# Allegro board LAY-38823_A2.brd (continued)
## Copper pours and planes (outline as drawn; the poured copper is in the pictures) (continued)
VSYS_5V on TOP (solid shape): 23.42,5.23 23.42,3.94 23.57,3.79 23.93,3.79 23.94,3.78 23.94,1.51 22.94,1.51 22.05,1.52 22.05,5.18 22.05,5.18 22.05,5.23 22.1,5.28 23.37,5.28
VSYS_5V on BOTTOM (solid shape): 22.15,5.44 22.35,5.44 22.35,6.28 22.55,6.28 22.55,5.44 22.75,5.44 22.75,6.28 22.95,6.28 22.95,5.44 23.15,5.44 23.15,6.28 23.35,6.28 23.35,4.17 21.95,4.17 21.95,6.28 22.15,6.28
VSYS_5V on BOTTOM (solid shape): 22.89,13.18 22.89,11.01 22.89,11.01 22.89,10.86 23.35,10.4 23.35,8.65 23.15,8.65 23.15,9.49 22.95,9.49 22.95,8.65 22.75,8.65 22.75,9.49 22.55,9.49 22.55,8.65 22.35,8.65 22.35,9.49 22.15,9.49 22.15,8.65 21.95,8.65 21.95,8.7 21.78,8.7 21.65,8.83 21.65,13.02 22.02,13.39 22.67,13.39
VSYS_5V on TOP: 13.03,10.67 14.25,10.67 14.65,10.26 14.65,9.7 14.55,9.6 13.08,9.6 12.9,9.78 12.9,10.54
VSYS_5V on TOP: 10.18,15.29 11,15.29 11.12,15.16 11.12,13.77 11.05,13.69 10.16,13.69 10.11,13.74 10.11,15.21
VSYS_5V on TOP: 7.69,7.77 8.63,7.77 8.71,7.7 8.71,6.43 8.51,6.22 7.87,6.22 7.69,6.4
VSYS_5V on L4_PWR_1: 5.64,15.59 11.99,15.59 12.93,14.66 14.32,14.66 14.63,14.35 14.63,7.34 14.04,6.75 10.15,6.75 9.26,5.87 7.92,5.87 6.86,6.93 6.86,7.67 6.25,8.28 5.76,8.28 5.31,8.74 5.31,15.26 ; 1 cut-out
VSYS_5V on L5_PWR_2: 8.08,16.13 12.86,16.13 15.36,13.63 15.36,13.21 24.79,13.21 24.79,5.01 23.67,3.89 21.36,3.89 20.32,4.93 8.71,4.93 7.1,6.54 7.1,6.95 7.52,7.37 12.14,7.37 13.74,8.97 13.74,13.13 13.13,13.74 8.89,13.74 7.87,14.76 7.87,15.93 ; 1 cut-out
N109658934 on TOP: 54.47,37.7 55.62,37.7 55.9,37.42 55.9,34.43 55.83,34.35 55.36,34.35 55.28,34.44 55.28,36.23 54.99,36.52 54.54,36.52 54.41,36.65 54.41,37.65

Small or netless copper shapes (teardrops, artwork), in the pictures only: 1 on L2_GND

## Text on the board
Ref Des/Silkscreen Bottom: GND | 5V0 | QSPI | 700-38823 REV A2 | SCH-38823 REV A2 | S/N
TOP: i.MX 8M NANO
Board Geometry/Soldermask Top: i.MX 8M NANO
Ref Des/Silkscreen Top: NVCC_SD2 | GND | 32K | CLK | CMD | DA0 | 24M | DQS | STATUS | RSTB | CKIN2 | CKIN1 | DQ0 | 1V2 | 1V8 | 0V8 | 3V3 | 1V1 | LPDDR4 | 0V9 | A1 | 5V0 | POR_B | ONOFF | ON_REQ | eMMC | SW1102 | SW1101 | WIFI&BT | WDOG | STBY | 8MNANOLPD4-EVK
DIMENSION: GRID ORIGIN | PRIMARY DATUM | BOARD | EDGE | TRACE ON TOP,WIDTH 11 MIL  50OHM (WIFI) | CORE | L2 GND | L3 IN1 | L4 PWR_1 | L5 PWR_2 | BOTTOM | PREPREG | TOP | 3.9 | 4.25 | 0.02 | THIS BOARD WAS DESIGNED FOR MAXIMUM FLEXIBILITY IN SOFTWARE DEVELOPMENT AND DEMONSTRATES | PRELIMINARY -SUBJECT TO CHANGE | NXP CONFIDENTIAL AND PROPRIETARY | MULTIPLE FUNCTIONS POSSIBLE WITH I.MX PROCESSORS. ALTHOUGH BEST DESIGN PRACTICES HAVE | BEEN APPLIED,SOME AREAS MAY NOT BE SUITABLE FOR A MASS-PRODUCTION DESIGN | 16 | 17 | 8 | DETAIL A
User.10: ALL PARTS, MATERIALS AND FINISHED | ASSEMBLY SHALL NOT CONTAIN ANY OF | THE SUBSTANCES OF VERY HIGH CONCERN | (SVHC) ABOVE THE THRESHOLD VALUE PER | THE CURRENT ECHA LIST OF SVHC'S AND | WITH ANNEX XIV AND ANNEX XVII OF REACH | DIRECTIVE 76/769/EEC. A CERTIFICATE OF | COMPLIANCE IS REQUIRED UPON REQUEST. | ASSEMBLY SHALL MEET THE RoHS | COMMISSION DELEGATED DIRECTIVE (EU) | 2015/863 OF 31 MARCH  2015 AMENDING | ANNEX II TO DIRECTIVE 2011/65/EU. A | CERTIFICATE OF COMPLIANCE IS | REQUIRED UPON REQUEST. | 07-01-18 | F.L. | B | NEW PMIC | NONE | 1
User.11: L6_BOTTOM | L3_IN1 | L1_TOP | 4.1 | 11 | 3.2 | 50 | 4.2 | 4.8 | 85 | 3.6 | 4.9 | 3 | 6
User.28: FIGURE | FINISHED_SIZE | 8.0 | 10.0 | 40.0 | 109.0 | 35.0 | 64.0 | DRILL CHART: TOP to BOTTOM | ALL UNITS ARE IN MILS | PLATED | NON-PLATED | QTY | 953 | 60 | 131 | 2 | 3 | 4
